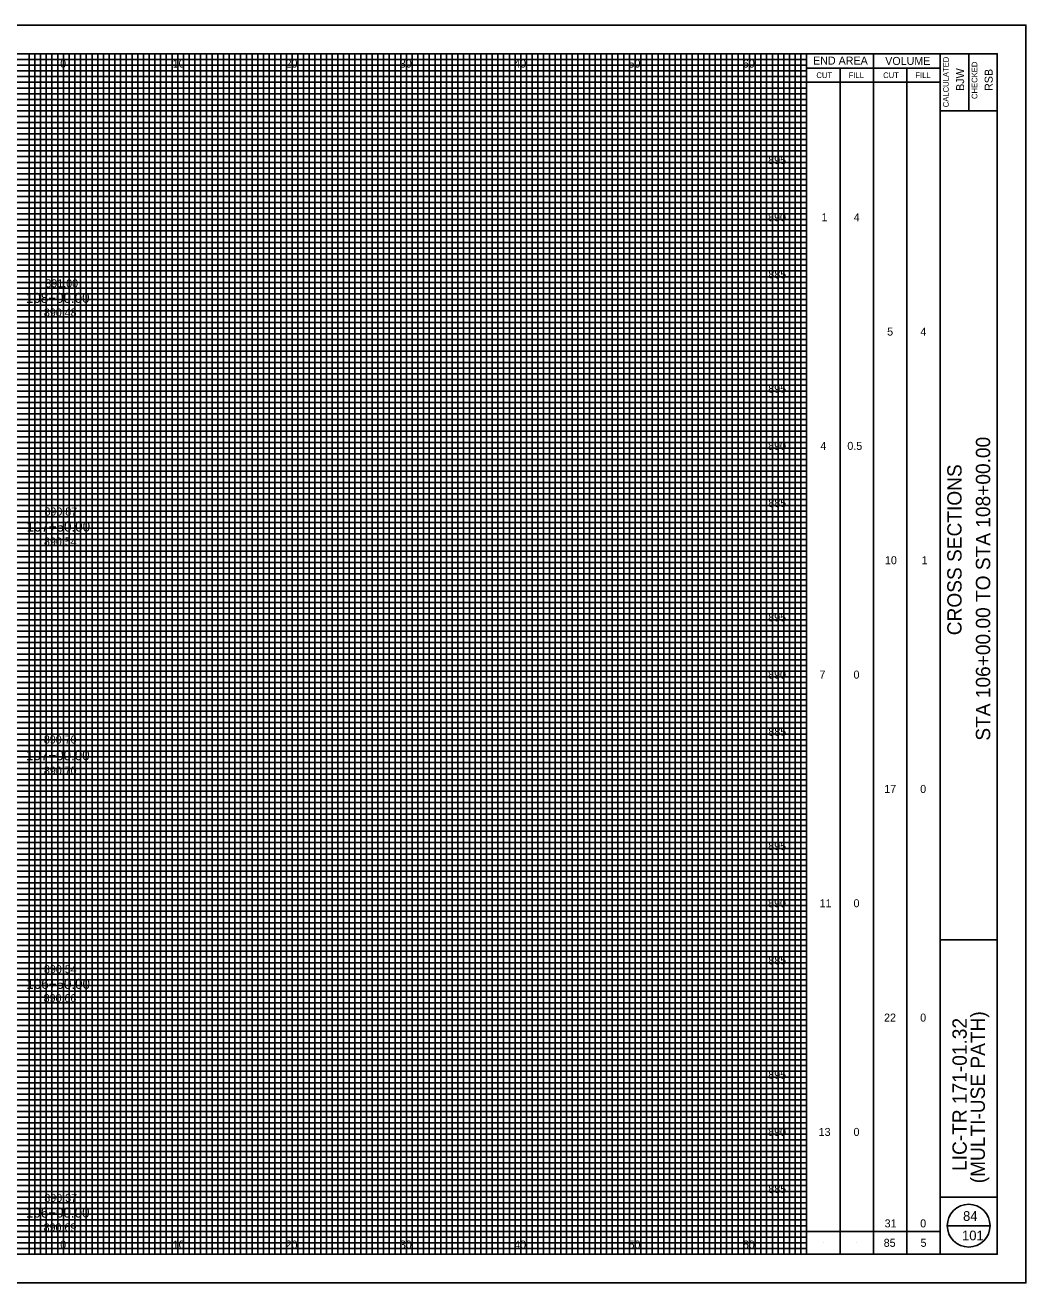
# Model space of a CAD drawing. Extents: x -10 to 160, y -2 to 3672.
# Drawn here: x 72.5 to 160, y 1722.5 to 1832.5 of the extents above; entities that cross this region are included whole.
import ezdxf

# ---------------------------------------------------------------- set-up
doc = ezdxf.new("R2010")
doc.units = 0
for name, color, linetype in [('SH_Border', 7, 'Continuous'), ('SH_Cut_Line', 7, 'Continuous'), ('SH_Data', 7, 'Continuous'), ('SH_Major_Grid_Line', 7, 'Continuous'), ('SH_Minor_Grid_Line', 7, 'Continuous'), ('SH_Text', 7, 'Continuous'), ('TX_P_10', 7, 'Continuous'), ('TX_X_10', 7, 'Continuous')]:
    doc.layers.add(name, color=color, linetype=linetype)

msp = doc.modelspace()

# ---------------------------------------------------------------- linework, layer by layer
at = {"layer": 'SH_Border'}
for p, q in [((152.5, 1725), (152.5, 1830)), ((155, 1830), (155, 1825)), ((152.5, 1825), (157.5, 1825)), ((152.5, 1752.5), (157.5, 1752.5)), ((152.5, 1730), (157.5, 1730))]:
    msp.add_line(p, q, dxfattribs=at)
msp.add_lwpolyline([(0, 1830), (157.5, 1830), (157.5, 1725), (0, 1725)], close=True, dxfattribs=at)
at = {"layer": 'SH_Cut_Line'}
msp.add_lwpolyline([(-10, 1722.5), (160, 1722.5), (160, 1832.5), (-10, 1832.5)], close=True, dxfattribs=at)
at = {"layer": 'SH_Data'}
for p, q in [((140.83, 1725), (140.83, 1830)), ((146.67, 1725), (146.67, 1830)), ((140.83, 1828.75), (152.5, 1828.75)), ((143.75, 1725), (143.75, 1828.75)), ((149.58, 1725), (149.58, 1828.75)), ((140.83, 1827.5), (152.5, 1827.5)), ((153.12, 1727.5), (156.88, 1727.5)), ((140.83, 1727), (152.5, 1727)), ((142.29, 1726), (142.29, 1726)), ((145.21, 1726), (145.21, 1726)), ((148.12, 1726), (148.12, 1726)), ((151.04, 1726), (151.04, 1726))]:
    msp.add_line(p, q, dxfattribs=at)
msp.add_circle((155, 1727.5), 1.87, dxfattribs=at)
at = {"layer": 'SH_Major_Grid_Line'}
for p, q in [((75.83, 1725), (75.83, 1830)), ((80.83, 1725), (80.83, 1830)), ((85.83, 1725), (85.83, 1830)), ((90.83, 1725), (90.83, 1830)), ((95.83, 1725), (95.83, 1830)), ((100.83, 1725), (100.83, 1830)), ((105.83, 1725), (105.83, 1830)), ((110.83, 1725), (110.83, 1830)), ((115.83, 1725), (115.83, 1830)), ((120.83, 1725), (120.83, 1830)), ((125.83, 1725), (125.83, 1830)), ((130.83, 1725), (130.83, 1830)), ((135.83, 1725), (135.83, 1830)), ((5.83, 1825), (140.83, 1825)), ((5.83, 1820), (140.83, 1820)), ((5.83, 1815), (140.83, 1815)), ((5.83, 1810), (140.83, 1810)), ((5.83, 1805), (140.83, 1805)), ((5.83, 1800), (140.83, 1800)), ((5.83, 1795), (140.83, 1795)), ((5.83, 1790), (140.83, 1790)), ((5.83, 1785), (140.83, 1785)), ((5.83, 1780), (140.83, 1780)), ((5.83, 1775), (140.83, 1775)), ((5.83, 1770), (140.83, 1770)), ((5.83, 1765), (140.83, 1765)), ((5.83, 1760), (140.83, 1760)), ((5.83, 1755), (140.83, 1755)), ((5.83, 1750), (140.83, 1750)), ((5.83, 1745), (140.83, 1745)), ((5.83, 1740), (140.83, 1740)), ((5.83, 1735), (140.83, 1735)), ((5.83, 1730), (140.83, 1730))]:
    msp.add_line(p, q, dxfattribs=at)
at = {"layer": 'SH_Minor_Grid_Line'}
for p, q in [((5.83, 1829.5), (140.83, 1829.5)), ((72.83, 1725), (72.83, 1830)), ((73.33, 1725), (73.33, 1830)), ((73.83, 1725), (73.83, 1830)), ((74.33, 1725), (74.33, 1830)), ((74.83, 1725), (74.83, 1830)), ((75.33, 1725), (75.33, 1830)), ((76.33, 1725), (76.33, 1830)), ((76.83, 1725), (76.83, 1830)), ((77.33, 1725), (77.33, 1830)), ((77.83, 1725), (77.83, 1830)), ((78.33, 1725), (78.33, 1830)), ((78.83, 1725), (78.83, 1830)), ((79.33, 1725), (79.33, 1830)), ((79.83, 1725), (79.83, 1830)), ((80.33, 1725), (80.33, 1830)), ((81.33, 1725), (81.33, 1830)), ((81.83, 1725), (81.83, 1830)), ((82.33, 1725), (82.33, 1830)), ((82.83, 1725), (82.83, 1830)), ((83.33, 1725), (83.33, 1830)), ((83.83, 1725), (83.83, 1830)), ((84.33, 1725), (84.33, 1830)), ((84.83, 1725), (84.83, 1830)), ((85.33, 1725), (85.33, 1830)), ((86.33, 1725), (86.33, 1830)), ((86.83, 1725), (86.83, 1830)), ((87.33, 1725), (87.33, 1830)), ((87.83, 1725), (87.83, 1830)), ((88.33, 1725), (88.33, 1830)), ((88.83, 1725), (88.83, 1830)), ((89.33, 1725), (89.33, 1830)), ((89.83, 1725), (89.83, 1830)), ((90.33, 1725), (90.33, 1830)), ((91.33, 1725), (91.33, 1830)), ((91.83, 1725), (91.83, 1830)), ((92.33, 1725), (92.33, 1830)), ((92.83, 1725), (92.83, 1830)), ((93.33, 1725), (93.33, 1830)), ((93.83, 1725), (93.83, 1830)), ((94.33, 1725), (94.33, 1830)), ((94.83, 1725), (94.83, 1830)), ((95.33, 1725), (95.33, 1830)), ((96.33, 1725), (96.33, 1830)), ((96.83, 1725), (96.83, 1830)), ((97.33, 1725), (97.33, 1830)), ((97.83, 1725), (97.83, 1830)), ((98.33, 1725), (98.33, 1830)), ((98.83, 1725), (98.83, 1830)), ((99.33, 1725), (99.33, 1830)), ((99.83, 1725), (99.83, 1830)), ((100.33, 1725), (100.33, 1830)), ((101.33, 1725), (101.33, 1830)), ((101.83, 1725), (101.83, 1830)), ((102.33, 1725), (102.33, 1830)), ((102.83, 1725), (102.83, 1830)), ((103.33, 1725), (103.33, 1830)), ((103.83, 1725), (103.83, 1830)), ((104.33, 1725), (104.33, 1830)), ((104.83, 1725), (104.83, 1830)), ((105.33, 1725), (105.33, 1830)), ((106.33, 1725), (106.33, 1830)), ((106.83, 1725), (106.83, 1830)), ((107.33, 1725), (107.33, 1830)), ((107.83, 1725), (107.83, 1830)), ((108.33, 1725), (108.33, 1830)), ((108.83, 1725), (108.83, 1830)), ((109.33, 1725), (109.33, 1830)), ((109.83, 1725), (109.83, 1830)), ((110.33, 1725), (110.33, 1830)), ((111.33, 1725), (111.33, 1830)), ((111.83, 1725), (111.83, 1830)), ((112.33, 1725), (112.33, 1830)), ((112.83, 1725), (112.83, 1830)), ((113.33, 1725), (113.33, 1830)), ((113.83, 1725), (113.83, 1830)), ((114.33, 1725), (114.33, 1830)), ((114.83, 1725), (114.83, 1830)), ((115.33, 1725), (115.33, 1830)), ((116.33, 1725), (116.33, 1830)), ((116.83, 1725), (116.83, 1830)), ((117.33, 1725), (117.33, 1830)), ((117.83, 1725), (117.83, 1830)), ((118.33, 1725), (118.33, 1830)), ((118.83, 1725), (118.83, 1830)), ((119.33, 1725), (119.33, 1830)), ((119.83, 1725), (119.83, 1830)), ((120.33, 1725), (120.33, 1830)), ((121.33, 1725), (121.33, 1830)), ((121.83, 1725), (121.83, 1830)), ((122.33, 1725), (122.33, 1830)), ((122.83, 1725), (122.83, 1830)), ((123.33, 1725), (123.33, 1830)), ((123.83, 1725), (123.83, 1830)), ((124.33, 1725), (124.33, 1830)), ((124.83, 1725), (124.83, 1830)), ((125.33, 1725), (125.33, 1830)), ((126.33, 1725), (126.33, 1830)), ((126.83, 1725), (126.83, 1830)), ((127.33, 1725), (127.33, 1830)), ((127.83, 1725), (127.83, 1830)), ((128.33, 1725), (128.33, 1830)), ((128.83, 1725), (128.83, 1830)), ((129.33, 1725), (129.33, 1830)), ((129.83, 1725), (129.83, 1830)), ((130.33, 1725), (130.33, 1830)), ((131.33, 1725), (131.33, 1830)), ((131.83, 1725), (131.83, 1830)), ((132.33, 1725), (132.33, 1830)), ((132.83, 1725), (132.83, 1830)), ((133.33, 1725), (133.33, 1830)), ((133.83, 1725), (133.83, 1830)), ((134.33, 1725), (134.33, 1830)), ((134.83, 1725), (134.83, 1830)), ((135.33, 1725), (135.33, 1830)), ((136.33, 1725), (136.33, 1830)), ((136.83, 1725), (136.83, 1830)), ((137.33, 1725), (137.33, 1830)), ((137.83, 1725), (137.83, 1830)), ((138.33, 1725), (138.33, 1830)), ((138.83, 1725), (138.83, 1830)), ((139.33, 1725), (139.33, 1830)), ((139.83, 1725), (139.83, 1830)), ((140.33, 1725), (140.33, 1830)), ((5.83, 1829), (140.83, 1829)), ((5.83, 1828.5), (140.83, 1828.5)), ((5.83, 1828), (140.83, 1828)), ((5.83, 1827.5), (140.83, 1827.5)), ((5.83, 1827), (140.83, 1827)), ((5.83, 1826.5), (140.83, 1826.5)), ((5.83, 1826), (140.83, 1826)), ((5.83, 1825.5), (140.83, 1825.5)), ((5.83, 1824.5), (140.83, 1824.5)), ((5.83, 1824), (140.83, 1824)), ((5.83, 1823.5), (140.83, 1823.5)), ((5.83, 1823), (140.83, 1823)), ((5.83, 1822.5), (140.83, 1822.5)), ((5.83, 1822), (140.83, 1822)), ((5.83, 1821.5), (140.83, 1821.5)), ((5.83, 1821), (140.83, 1821)), ((5.83, 1820.5), (140.83, 1820.5)), ((5.83, 1819.5), (140.83, 1819.5)), ((5.83, 1819), (140.83, 1819)), ((5.83, 1818.5), (140.83, 1818.5)), ((5.83, 1818), (140.83, 1818)), ((5.83, 1817.5), (140.83, 1817.5)), ((5.83, 1817), (140.83, 1817)), ((5.83, 1816.5), (140.83, 1816.5)), ((5.83, 1816), (140.83, 1816)), ((5.83, 1815.5), (140.83, 1815.5)), ((5.83, 1814.5), (140.83, 1814.5)), ((5.83, 1814), (140.83, 1814)), ((5.83, 1813.5), (140.83, 1813.5)), ((5.83, 1813), (140.83, 1813)), ((5.83, 1812.5), (140.83, 1812.5)), ((5.83, 1812), (140.83, 1812)), ((5.83, 1811.5), (140.83, 1811.5)), ((5.83, 1811), (140.83, 1811)), ((5.83, 1810.5), (140.83, 1810.5)), ((5.83, 1809.5), (140.83, 1809.5)), ((5.83, 1809), (140.83, 1809)), ((5.83, 1808.5), (140.83, 1808.5)), ((5.83, 1808), (140.83, 1808)), ((5.83, 1807.5), (140.83, 1807.5)), ((5.83, 1807), (140.83, 1807)), ((5.83, 1806.5), (140.83, 1806.5)), ((5.83, 1806), (140.83, 1806)), ((5.83, 1805.5), (140.83, 1805.5)), ((5.83, 1804.5), (140.83, 1804.5)), ((5.83, 1804), (140.83, 1804)), ((5.83, 1803.5), (140.83, 1803.5)), ((5.83, 1803), (140.83, 1803)), ((5.83, 1802.5), (140.83, 1802.5)), ((5.83, 1802), (140.83, 1802)), ((5.83, 1801.5), (140.83, 1801.5)), ((5.83, 1801), (140.83, 1801)), ((5.83, 1800.5), (140.83, 1800.5)), ((5.83, 1799.5), (140.83, 1799.5)), ((5.83, 1799), (140.83, 1799)), ((5.83, 1798.5), (140.83, 1798.5)), ((5.83, 1798), (140.83, 1798)), ((5.83, 1797.5), (140.83, 1797.5)), ((5.83, 1797), (140.83, 1797)), ((5.83, 1796.5), (140.83, 1796.5)), ((5.83, 1796), (140.83, 1796)), ((5.83, 1795.5), (140.83, 1795.5)), ((5.83, 1794.5), (140.83, 1794.5)), ((5.83, 1794), (140.83, 1794)), ((5.83, 1793.5), (140.83, 1793.5)), ((5.83, 1793), (140.83, 1793)), ((5.83, 1792.5), (140.83, 1792.5)), ((5.83, 1792), (140.83, 1792)), ((5.83, 1791.5), (140.83, 1791.5)), ((5.83, 1791), (140.83, 1791)), ((5.83, 1790.5), (140.83, 1790.5)), ((5.83, 1789.5), (140.83, 1789.5)), ((5.83, 1789), (140.83, 1789)), ((5.83, 1788.5), (140.83, 1788.5)), ((5.83, 1788), (140.83, 1788)), ((5.83, 1787.5), (140.83, 1787.5)), ((5.83, 1787), (140.83, 1787)), ((5.83, 1786.5), (140.83, 1786.5)), ((5.83, 1786), (140.83, 1786)), ((5.83, 1785.5), (140.83, 1785.5)), ((5.83, 1784.5), (140.83, 1784.5)), ((5.83, 1784), (140.83, 1784)), ((5.83, 1783.5), (140.83, 1783.5)), ((5.83, 1783), (140.83, 1783)), ((5.83, 1782.5), (140.83, 1782.5)), ((5.83, 1782), (140.83, 1782)), ((5.83, 1781.5), (140.83, 1781.5)), ((5.83, 1781), (140.83, 1781)), ((5.83, 1780.5), (140.83, 1780.5)), ((5.83, 1779.5), (140.83, 1779.5)), ((5.83, 1779), (140.83, 1779)), ((5.83, 1778.5), (140.83, 1778.5)), ((5.83, 1778), (140.83, 1778)), ((5.83, 1777.5), (140.83, 1777.5)), ((5.83, 1777), (140.83, 1777)), ((5.83, 1776.5), (140.83, 1776.5)), ((5.83, 1776), (140.83, 1776)), ((5.83, 1775.5), (140.83, 1775.5)), ((5.83, 1774.5), (140.83, 1774.5)), ((5.83, 1774), (140.83, 1774)), ((5.83, 1773.5), (140.83, 1773.5)), ((5.83, 1773), (140.83, 1773)), ((5.83, 1772.5), (140.83, 1772.5)), ((5.83, 1772), (140.83, 1772)), ((5.83, 1771.5), (140.83, 1771.5)), ((5.83, 1771), (140.83, 1771)), ((5.83, 1770.5), (140.83, 1770.5)), ((5.83, 1769.5), (140.83, 1769.5)), ((5.83, 1769), (140.83, 1769)), ((5.83, 1768.5), (140.83, 1768.5)), ((5.83, 1768), (140.83, 1768)), ((5.83, 1767.5), (140.83, 1767.5)), ((5.83, 1767), (140.83, 1767)), ((5.83, 1766.5), (140.83, 1766.5)), ((5.83, 1766), (140.83, 1766)), ((5.83, 1765.5), (140.83, 1765.5)), ((5.83, 1764.5), (140.83, 1764.5)), ((5.83, 1764), (140.83, 1764)), ((5.83, 1763.5), (140.83, 1763.5)), ((5.83, 1763), (140.83, 1763)), ((5.83, 1762.5), (140.83, 1762.5)), ((5.83, 1762), (140.83, 1762)), ((5.83, 1761.5), (140.83, 1761.5)), ((5.83, 1761), (140.83, 1761)), ((5.83, 1760.5), (140.83, 1760.5)), ((5.83, 1759.5), (140.83, 1759.5)), ((5.83, 1759), (140.83, 1759)), ((5.83, 1758.5), (140.83, 1758.5)), ((5.83, 1758), (140.83, 1758)), ((5.83, 1757.5), (140.83, 1757.5)), ((5.83, 1757), (140.83, 1757)), ((5.83, 1756.5), (140.83, 1756.5)), ((5.83, 1756), (140.83, 1756)), ((5.83, 1755.5), (140.83, 1755.5)), ((5.83, 1754.5), (140.83, 1754.5)), ((5.83, 1754), (140.83, 1754)), ((5.83, 1753.5), (140.83, 1753.5)), ((5.83, 1753), (140.83, 1753)), ((5.83, 1752.5), (140.83, 1752.5)), ((5.83, 1752), (140.83, 1752)), ((5.83, 1751.5), (140.83, 1751.5)), ((5.83, 1751), (140.83, 1751)), ((5.83, 1750.5), (140.83, 1750.5)), ((5.83, 1749.5), (140.83, 1749.5)), ((5.83, 1749), (140.83, 1749)), ((5.83, 1748.5), (140.83, 1748.5)), ((5.83, 1748), (140.83, 1748)), ((5.83, 1747.5), (140.83, 1747.5)), ((5.83, 1747), (140.83, 1747)), ((5.83, 1746.5), (140.83, 1746.5)), ((5.83, 1746), (140.83, 1746)), ((5.83, 1745.5), (140.83, 1745.5)), ((5.83, 1744.5), (140.83, 1744.5)), ((5.83, 1744), (140.83, 1744)), ((5.83, 1743.5), (140.83, 1743.5)), ((5.83, 1743), (140.83, 1743)), ((5.83, 1742.5), (140.83, 1742.5)), ((5.83, 1742), (140.83, 1742)), ((5.83, 1741.5), (140.83, 1741.5)), ((5.83, 1741), (140.83, 1741)), ((5.83, 1740.5), (140.83, 1740.5)), ((5.83, 1739.5), (140.83, 1739.5)), ((5.83, 1739), (140.83, 1739)), ((5.83, 1738.5), (140.83, 1738.5)), ((5.83, 1738), (140.83, 1738)), ((5.83, 1737.5), (140.83, 1737.5)), ((5.83, 1737), (140.83, 1737)), ((5.83, 1736.5), (140.83, 1736.5)), ((5.83, 1736), (140.83, 1736)), ((5.83, 1735.5), (140.83, 1735.5)), ((5.83, 1734.5), (140.83, 1734.5)), ((5.83, 1734), (140.83, 1734)), ((5.83, 1733.5), (140.83, 1733.5)), ((5.83, 1733), (140.83, 1733)), ((5.83, 1732.5), (140.83, 1732.5)), ((5.83, 1732), (140.83, 1732)), ((5.83, 1731.5), (140.83, 1731.5)), ((5.83, 1731), (140.83, 1731)), ((5.83, 1730.5), (140.83, 1730.5)), ((5.83, 1729.5), (140.83, 1729.5)), ((5.83, 1729), (140.83, 1729)), ((5.83, 1728.5), (140.83, 1728.5)), ((5.83, 1728), (140.83, 1728)), ((5.83, 1727.5), (140.83, 1727.5)), ((5.83, 1727), (140.83, 1727)), ((5.83, 1726.5), (140.83, 1726.5)), ((5.83, 1726), (140.83, 1726)), ((5.83, 1725.5), (140.83, 1725.5))]:
    msp.add_line(p, q, dxfattribs=at)

# ---------------------------------------------------------------- texts
at = {"layer": 'SH_Data'}
for s, height, p in [('END AREA', 0.7, (141.39, 1829.05)), ('VOLUME', 0.7, (147.7, 1829.02)), ('CUT', 0.5, (141.68, 1827.87)), ('FILL', 0.5, (144.5, 1827.87)), ('CUT', 0.5, (147.52, 1827.87)), ('FILL', 0.5, (150.34, 1827.87)), ('84', 0.85, (154.51, 1727.92)), ('101', 0.85, (154.42, 1726.22))]:
    msp.add_text(s, height=height, dxfattribs=at).set_placement(p)
for s, height, p in [('CALCULATED', 0.5, (153.26, 1825.32)), ('BJW', 0.7, (154.6, 1826.75)), ('CHECKED', 0.5, (155.76, 1826.04)), ('RSB', 0.7, (157.1, 1826.75)), ('STA 106+00.00 TO STA 108+00.00', 1.25, (156.88, 1769.92)), ('CROSS SECTIONS', 1.25, (154.38, 1779.14)), ('(MULTI-USE PATH)', 1.25, (156.42, 1731.21)), ('LIC-TR 171-01.32', 1.25, (154.83, 1732.29))]:
    msp.add_text(s, height=height, rotation=90, dxfattribs=at).set_placement(p)
at = {"layer": 'SH_Text'}
for s, height, p in [('0', 0.7, (75.55, 1828.79)), ('10', 0.7, (85.39, 1828.79)), ('20', 0.7, (95.26, 1828.79)), ('30', 0.7, (105.25, 1828.79)), ('40', 0.7, (115.25, 1828.79)), ('50', 0.7, (125.25, 1828.79)), ('60', 0.7, (135.25, 1828.79)), ('895', 0.7, (137.47, 1820.35)), ('890', 0.7, (137.46, 1815.35)), ('1', 0.7, (142.13, 1815.35)), ('4', 0.7, (144.95, 1815.35)), ('885', 0.7, (137.48, 1810.35)), ('108+00.00', 0.875, (72.55, 1808.21)), ('5', 0.7, (147.87, 1805.35)), ('4', 0.7, (150.78, 1805.35)), ('895', 0.7, (137.47, 1800.35)), ('890', 0.7, (137.46, 1795.35)), ('4', 0.7, (142.03, 1795.35)), ('0.5', 0.7, (144.39, 1795.35)), ('885', 0.7, (137.48, 1790.35)), ('107+50.00', 0.875, (72.6, 1788.21)), ('10', 0.7, (147.68, 1785.35)), ('1', 0.7, (150.88, 1785.35)), ('895', 0.7, (137.47, 1780.35)), ('890', 0.7, (137.46, 1775.35)), ('7', 0.7, (141.95, 1775.35)), ('0', 0.7, (144.93, 1775.35)), ('885', 0.7, (137.48, 1770.35)), ('107+00.00', 0.875, (72.56, 1768.21)), ('17', 0.7, (147.62, 1765.35)), ('0', 0.7, (150.76, 1765.35)), ('895', 0.7, (137.47, 1760.35)), ('890', 0.7, (137.46, 1755.35)), ('11', 0.7, (141.96, 1755.35)), ('0', 0.7, (144.93, 1755.35)), ('885', 0.7, (137.48, 1750.35)), ('106+50.00', 0.875, (72.59, 1748.21)), ('22', 0.7, (147.6, 1745.35)), ('0', 0.7, (150.76, 1745.35)), ('895', 0.7, (137.47, 1740.35)), ('890', 0.7, (137.46, 1735.35)), ('13', 0.7, (141.88, 1735.35)), ('0', 0.7, (144.93, 1735.35)), ('885', 0.7, (137.48, 1730.35)), ('106+00.00', 0.875, (72.55, 1728.21)), ('31', 0.7, (147.65, 1727.35)), ('0', 0.7, (150.76, 1727.35)), ('0', 0.7, (75.55, 1725.5)), ('10', 0.7, (85.39, 1725.5)), ('20', 0.7, (95.26, 1725.5)), ('30', 0.7, (105.25, 1725.5)), ('40', 0.7, (115.25, 1725.5)), ('50', 0.7, (125.25, 1725.5)), ('60', 0.7, (135.25, 1725.5)), ('85', 0.7, (147.57, 1725.65)), ('5', 0.7, (150.79, 1725.65))]:
    msp.add_text(s, height=height, dxfattribs=at).set_placement(p)
at = {"layer": 'TX_P_10'}
for s, p in [('891.00', (74.25, 1809.57)), ('890.87', (74.17, 1789.61)), ('890.70', (74.12, 1769.67)), ('890.54', (74.13, 1749.58)), ('890.37', (74.16, 1729.58))]:
    msp.add_text(s, height=0.7, dxfattribs=at).set_placement(p)
at = {"layer": 'TX_X_10'}
for s, p in [('890.48', (74.12, 1807.02)), ('890.54', (74.13, 1786.99)), ('890.70', (74.12, 1766.95)), ('890.66', (74.1, 1747.05)), ('890.69', (74.1, 1727))]:
    msp.add_text(s, height=0.7, dxfattribs=at).set_placement(p)

doc.saveas('drawing.dxf')
